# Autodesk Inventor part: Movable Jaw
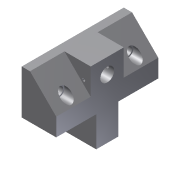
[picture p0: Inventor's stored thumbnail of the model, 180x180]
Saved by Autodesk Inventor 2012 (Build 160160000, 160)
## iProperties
Shininess: 77.0
Length Units: 11269
Angle Units: 11279
Time Units: 11290
Mass Units: 11283
Length Display Precision: 3
Angle Display Precision: 2
Created: 2002-02
Part Number: Movable Jaw
Document SubType Name: Modeling
Designer: ***
Density: 1 g/cm^3
Material: Default
Mass: 56.5592 g
Surface Area: 124.284 cm^2
Volume: 56.5592 cm^3
Density: 0.0
Volumn: 0.0
Area: 0.0
PropertySet Name: Model Information
Control State: 0
Master: False
Checked Out: False
Author: ***
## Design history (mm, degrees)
sketch "Sketch2"
  geometry: L1 (2.39, 41.509)-(2.39, 9.509); L2 (2.39, 9.509)-(-22.61, 9.509); L3 (-22.61, 9.509)-(-22.61, 22.509); L4 (-22.61, 22.509)-(-3.61, 41.509); L5 (-3.61, 41.509)-(2.39, 41.509)
  constraints: 10 end point, 2 parallel, 1 perpendicular, 1 vertical
  dimensions: "d0" = 25 distance of L1.end L2.end; "d2" = 13 distance of L2.end L3.end; "d3" = 32 distance between parallel lines of L5 L2; "d4" = 6 distance of L4.end L1.start
extrude "Extrusion1" new body sketch "Sketch2" stored distance "d5" = 74; taper "d6" = 0 deg
sketch "Sketch3"
  geometry: L1 (-19, 25)-(11, 25); L2 (11, 25)-(11, 49); L3 (11, 49)-(-19, 49); L4 (-19, 49)-(-19, 25); L5 (0, 0)-(13, 0) reference; L6 (-19, 74)-(-19, 0) reference; L7 (11.924, 29)-(35, 29); L8 (35, 29)-(35, 45); L9 (35, 45)-(11.924, 45); L10 (11.924, 45)-(11.924, 29); L11 (13, 74)-(13, 0) reference
  constraints: 16 end point, 4 parallel, 2 horizontal, 2 perpendicular, 1 collinear
  dimensions: "d7" = 24 distance of L3.end L1.start; "d8" = 30 distance of L1.start L1.end; "d9" = 25 distance between parallel lines of L5 L1; "d10" = 16 distance of L7.end L8.end; "d11" = 4 distance between parallel lines of L3 L9; "d12" = 22 distance between parallel lines of L11 L8
extrude "Extrusion2" join sketch "Sketch3" distance "d13" = 25; taper "d14" = 0 deg
sketch "Sketch4"
  geometry: L1 (-19, -25)-(-19, -49) reference; L2 (-19, -49)-(0, -49) reference; 1 further point
  dimensions: "d15" = 11 distance from line of L1 point (-8, -37); "d16" = 12 distance from line of L2 point (-8, -37)
hole "Hole1" sketch "Sketch4" at (-8, -37) diameter "d17" = 10; stored, may be unused: countersink angle "d21" = 82 deg, drill point angle "d23" = 0 deg; dims "d18" = 6, "d19" = 4, "d20" = 2, "d22" = 13
sketch "Sketch5"
  geometry: L1 (-19, -49)-(-19, -74) reference; L2 (0, -74)-(13, -74) reference; 1 further point
  dimensions: "d24" = 14 distance from line of L1 point (-5, -62); "d25" = 12 distance from line of L2 point (-5, -62)
hole "Hole2" sketch "Sketch5" at (-5, -62) diameter "d26" = 6; stored, may be unused: countersink angle "d30" = 82 deg, drill point angle "d32" = 0 deg; dims "d27" = 6, "d28" = 8, "d29" = 10, "d31" = 13
mirror "Mirror1"
sketch "Sketch6"
  geometry: L1 (0, 19)-(0, 0) reference; 1 further point
  dimensions: "d33" = 5 distance from line of L1 point (-5, 8); "d34" = 11 vertical distance of L1.start point (-5, 8)
hole "Hole3" sketch "Sketch6" at (-5, 8) diameter "d35" = 2; stored, may be unused: countersink angle "d39" = 82 deg, drill point angle "d41" = 0 deg; dims "d36" = 6, "d37" = 8, "d38" = 10, "d40" = 13
body "Solid1"
